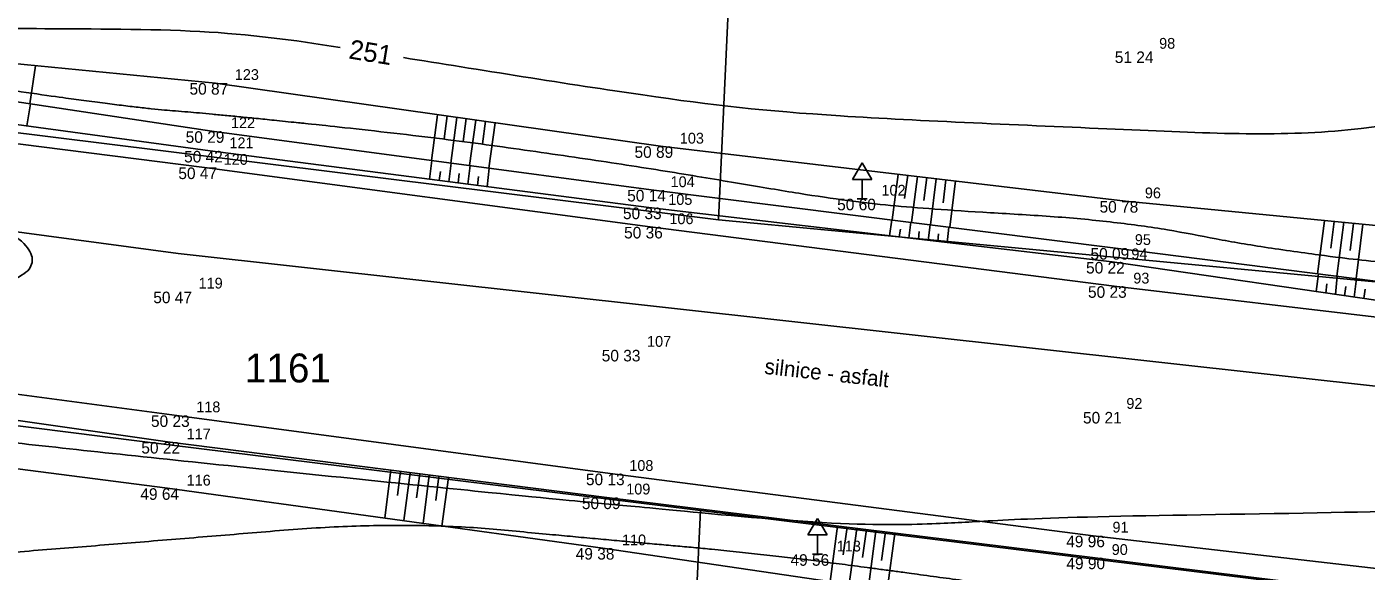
# Model space of a CAD drawing. Extents: x -704057 to -703795, y -1008732 to -1008584.
# Drawn here: x -703910.66 to -703875.92, y -1008669.28 to -1008655.16 of the extents above; entities that cross this region are included whole.
import ezdxf

# ---------------------------------------------------------------- set-up
doc = ezdxf.new("R2010")
doc.units = 0
for name, color, linetype in [('Z_body', 7, 'Continuous'), ('Z_body_cisla', 7, 'Continuous'), ('Z_body_vysky', 7, 'Continuous'), ('Z_dopravni_znaceni', 7, 'Continuous'), ('Z_katastr_cisla_pozemkove', 7, 'Continuous'), ('Z_katastr_hranice', 7, 'Continuous'), ('Z_katastr_hranice_KU', 7, 'Continuous'), ('Z_katastr_vnitrni_kresba', 7, 'Continuous'), ('Z_komunikace_zpevn_pl', 7, 'Continuous'), ('Z_popis', 7, 'Continuous'), ('Z_teren_hrany_paty', 7, 'Continuous'), ('Z_vrstevnice_popis', 7, 'Continuous'), ('Z_vrstevnice_vedlejsi', 7, 'Continuous')]:
    doc.layers.add(name, color=color, linetype=linetype)

# ---------------------------------------------------------------- blocks, each defined once
blk = doc.blocks.new('POINT_DISPLAY')
blk.add_line((0, 0), (0, 0))
blk = doc.blocks.new('Z527')
for p, q in [((0, 0.93), (-0.25, 0.5)), ((0.25, 0.5), (0, 0.93)), ((-0.25, 0.5), (0.25, 0.5)), ((0, 0), (0, 0.5)), ((-0.13, 0), (0.13, 0))]:
    blk.add_line(p, q)

msp = doc.modelspace()

# ---------------------------------------------------------------- linework, layer by layer
at = {"layer": 'Z_katastr_hranice'}
for p, q in [((-703892.72, -1008660.17), (-703891.93, -1008643.46)), ((-703913.69, -1008657.56), (-703892.72, -1008660.17)), ((-703892.72, -1008660.17), (-703821.1, -1008666.93)), ((-703947.65, -1008660.85), (-703907.73, -1008665.91)), ((-703907.73, -1008665.91), (-703871.83, -1008670.35))]:
    msp.add_line(p, q, dxfattribs=at)
at = {"layer": 'Z_katastr_hranice_KU'}
for p, q in [((-703947.15, -1008655.63), (-703906.73, -1008661.04)), ((-703906.73, -1008661.04), (-703853.02, -1008667))]:
    msp.add_line(p, q, dxfattribs=at)
at = {"layer": 'Z_katastr_vnitrni_kresba'}
msp.add_line((-703894.62, -1008696.05), (-703893.18, -1008667.71), dxfattribs=at)
at = {"layer": 'Z_komunikace_zpevn_pl'}
for p, q in [((-703906.05, -1008658.81), (-703916.99, -1008657.43)), ((-703894.49, -1008660.35), (-703906.05, -1008658.81)), ((-703882.46, -1008661.89), (-703894.49, -1008660.35)), ((-703870.13, -1008663.35), (-703882.46, -1008661.89)), ((-703917.71, -1008663.78), (-703906.76, -1008665.24)), ((-703906.76, -1008665.24), (-703895.53, -1008666.75)), ((-703895.53, -1008666.75), (-703883, -1008668.36)), ((-703883, -1008668.36), (-703870.95, -1008669.76))]:
    msp.add_line(p, q, dxfattribs=at)
at = {"layer": 'Z_teren_hrany_paty'}
for p, q in [((-703905.76, -1008656.62), (-703912.17, -1008656)), ((-703910.43, -1008656.17), (-703910.58, -1008657.16)), ((-703913.61, -1008656.7), (-703905.86, -1008657.87)), ((-703894.22, -1008658.26), (-703905.76, -1008656.62)), ((-703910.65, -1008657.73), (-703910.56, -1008657.16)), ((-703905.9, -1008658.38), (-703913.8, -1008657.3)), ((-703900, -1008657.44), (-703900.16, -1008658.63)), ((-703899.75, -1008657.47), (-703899.83, -1008658.07)), ((-703899.5, -1008657.51), (-703899.66, -1008658.7)), ((-703899.26, -1008657.54), (-703899.34, -1008658.14)), ((-703899.01, -1008657.58), (-703899.17, -1008658.76)), ((-703898.76, -1008657.61), (-703898.84, -1008658.2)), ((-703898.51, -1008657.65), (-703898.67, -1008658.83)), ((-703905.86, -1008657.87), (-703894.46, -1008659.39)), ((-703894.52, -1008659.85), (-703905.9, -1008658.38)), ((-703882.16, -1008659.68), (-703894.22, -1008658.26)), ((-703900.21, -1008659.11), (-703900.15, -1008658.63)), ((-703899.71, -1008659.18), (-703899.65, -1008658.7)), ((-703899.22, -1008659.24), (-703899.16, -1008658.76)), ((-703898.72, -1008659.31), (-703898.66, -1008658.83)), ((-703899.96, -1008659.15), (-703899.93, -1008658.91)), ((-703899.47, -1008659.21), (-703899.44, -1008658.97)), ((-703898.97, -1008659.28), (-703898.94, -1008659.04)), ((-703888.06, -1008658.99), (-703888.21, -1008660.17)), ((-703887.81, -1008659.01), (-703887.89, -1008659.61)), ((-703887.56, -1008659.04), (-703887.71, -1008660.24)), ((-703887.31, -1008659.07), (-703887.39, -1008659.67)), ((-703887.07, -1008659.1), (-703887.22, -1008660.3)), ((-703886.82, -1008659.13), (-703886.89, -1008659.73)), ((-703886.57, -1008659.16), (-703886.72, -1008660.36)), ((-703894.46, -1008659.39), (-703882.42, -1008660.9)), ((-703882.51, -1008661.26), (-703894.52, -1008659.85)), ((-703869.72, -1008660.9), (-703882.16, -1008659.68)), ((-703888.28, -1008660.58), (-703888.22, -1008660.17)), ((-703887.78, -1008660.64), (-703887.73, -1008660.23)), ((-703877, -1008660.19), (-703877.18, -1008661.57)), ((-703876.75, -1008660.21), (-703876.84, -1008660.9)), ((-703876.5, -1008660.23), (-703876.68, -1008661.63)), ((-703876.25, -1008660.26), (-703876.34, -1008660.96)), ((-703876.01, -1008660.28), (-703876.18, -1008661.69)), ((-703888.03, -1008660.61), (-703888, -1008660.41)), ((-703887.53, -1008660.67), (-703887.51, -1008660.47)), ((-703887.28, -1008660.7), (-703887.23, -1008660.3)), ((-703887.03, -1008660.73), (-703887.01, -1008660.53)), ((-703886.79, -1008660.76), (-703886.74, -1008660.36)), ((-703882.42, -1008660.9), (-703870.05, -1008662.47)), ((-703870.14, -1008663.06), (-703882.51, -1008661.26)), ((-703877.22, -1008662.03), (-703877.16, -1008661.57)), ((-703876.72, -1008662.1), (-703876.67, -1008661.63)), ((-703876.97, -1008662.07), (-703876.94, -1008661.83)), ((-703876.48, -1008662.14), (-703876.45, -1008661.9)), ((-703876.23, -1008662.17), (-703876.17, -1008661.69)), ((-703875.98, -1008662.21), (-703875.95, -1008661.97)), ((-703907.01, -1008665.93), (-703917.78, -1008664.39)), ((-703918.14, -1008665.69), (-703907.01, -1008667.13)), ((-703895.61, -1008667.37), (-703907.01, -1008665.93)), ((-703901.21, -1008666.66), (-703901.37, -1008667.9)), ((-703900.96, -1008666.69), (-703901.04, -1008667.32)), ((-703900.71, -1008666.73), (-703900.88, -1008667.97)), ((-703900.46, -1008666.76), (-703900.55, -1008667.38)), ((-703900.22, -1008666.79), (-703900.38, -1008668.04)), ((-703899.97, -1008666.82), (-703900.05, -1008667.45)), ((-703899.72, -1008666.85), (-703899.89, -1008668.11)), ((-703907.01, -1008667.13), (-703895.72, -1008668.68)), ((-703883.02, -1008668.93), (-703895.61, -1008667.37)), ((-703889.63, -1008668.11), (-703889.82, -1008669.55)), ((-703889.38, -1008668.14), (-703889.48, -1008668.86)), ((-703889.13, -1008668.17), (-703889.33, -1008669.62)), ((-703888.88, -1008668.2), (-703888.98, -1008668.93)), ((-703888.64, -1008668.23), (-703888.83, -1008669.69)), ((-703888.39, -1008668.26), (-703888.49, -1008669)), ((-703888.14, -1008668.3), (-703888.34, -1008669.77)), ((-703895.72, -1008668.68), (-703883.41, -1008670.49)), ((-703871.14, -1008670.4), (-703883.02, -1008668.93))]:
    msp.add_line(p, q, dxfattribs=at)
at = {"layer": 'Z_vrstevnice_popis'}
for points in [[(-703958.782, -1008656.452), (-703958.711, -1008656.345), (-703958.126, -1008655.591), (-703956.246, -1008655.482), (-703959.788, -1008654.246), (-703961.93, -1008651.293), (-703961.78, -1008651.126), (-703959.248, -1008651.187), (-703958.2, -1008651.305), (-703958.136, -1008651.315), (-703958.106, -1008651.318), (-703958.062, -1008651.325), (-703957.976, -1008651.334), (-703949.197, -1008652.35), (-703949.055, -1008652.366), (-703948.978, -1008652.372), (-703948.89, -1008652.368), (-703940.582, -1008653.06), (-703940.108, -1008653.095), (-703933.647, -1008653.758), (-703931.403, -1008653.997), (-703930.745, -1008653.985), (-703930.26, -1008654), (-703929.245, -1008652.825), (-703928.701, -1008652.453), (-703928.643, -1008652.6), (-703928.429, -1008652.279), (-703926.218, -1008652.574), (-703924.884, -1008652.504), (-703924.716, -1008652.484), (-703922.063, -1008653.995), (-703921.911, -1008654.006), (-703921.781, -1008654.024), (-703921.558, -1008654.048), (-703920.173, -1008654.162), (-703919.91, -1008654.188), (-703916.508, -1008654.023), (-703914.694, -1008654.331), (-703914.465, -1008654.432), (-703913.706, -1008654.968), (-703913.145, -1008655.151), (-703910.497, -1008655.228), (-703905.972, -1008655.203), (-703903.752, -1008655.504), (-703902.532, -1008655.695)], [(-703900.886, -1008655.959), (-703899.024, -1008656.26), (-703894.071, -1008657.056), (-703890.313, -1008657.487), (-703881.983, -1008657.824), (-703876.324, -1008658.109), (-703871.084, -1008656.76), (-703869.237, -1008656.583), (-703868.601, -1008656.623), (-703856.36, -1008656.952), (-703852.392, -1008657.193), (-703842.819, -1008657.404), (-703836.655, -1008657.542), (-703831.19, -1008657.812), (-703826.999, -1008658.179), (-703824.254, -1008658.442), (-703823.966, -1008658.47)], [(-703935.451, -1008665.426), (-703935.149, -1008665.04), (-703935.119, -1008664.898), (-703935.079, -1008664.688), (-703934.778, -1008664.597), (-703933.704, -1008664.644), (-703930.729, -1008663.86), (-703930.56, -1008663.863), (-703922.686, -1008664.709), (-703917.99, -1008665.148), (-703912.22, -1008665.818), (-703907.01, -1008666.385), (-703897.89, -1008667.322), (-703895.624, -1008667.536), (-703894.683, -1008667.62), (-703889.646, -1008668.109), (-703886.88, -1008668.055), (-703885.948, -1008667.981), (-703882.942, -1008667.846), (-703876.005, -1008667.766), (-703871.926, -1008667.612), (-703869.247, -1008667.54), (-703868.688, -1008667.52)]]:
    msp.add_open_spline(points, degree=3, dxfattribs=at)
at = {"layer": 'Z_vrstevnice_vedlejsi'}
for points in [[(-703944.218, -1008669.537), (-703942.215, -1008669.847), (-703941.835, -1008669.79), (-703940.983, -1008669.911), (-703940.538, -1008669.059), (-703940.441, -1008669.011), (-703939.659, -1008668.87), (-703938.392, -1008666.573), (-703937.218, -1008665.198), (-703936.994, -1008664.158), (-703936.811, -1008663.182), (-703935.504, -1008662.788), (-703930.851, -1008662.989), (-703930.683, -1008662.945), (-703930.514, -1008662.948), (-703928.53, -1008663.14), (-703926.451, -1008662.869), (-703924.285, -1008662.962), (-703918.453, -1008660.188), (-703917.529, -1008662.583), (-703908.804, -1008661.73), (-703914.417, -1008658.58), (-703914.255, -1008657.775), (-703916.458, -1008657.408), (-703916.075, -1008656.975), (-703916.505, -1008656.883), (-703916.435, -1008655.703), (-703915.746, -1008656.007), (-703915.438, -1008656.225), (-703913.541, -1008656.36), (-703913.202, -1008656.502), (-703907.93, -1008657.256), (-703905.824, -1008657.417), (-703900.033, -1008658.024), (-703894.345, -1008658.848), (-703890.179, -1008659.57), (-703887.702, -1008659.871), (-703882.266, -1008660.175), (-703878.347, -1008660.959), (-703873.149, -1008661.531), (-703869.803, -1008661.293), (-703867.148, -1008661.514), (-703856.66, -1008662.48), (-703848.555, -1008661.935), (-703843.582, -1008661.747), (-703840.018, -1008661.713), (-703835.656, -1008661.182), (-703832.168, -1008661.259), (-703831.497, -1008661.293), (-703819.488, -1008662.346), (-703817.521, -1008662.543), (-703807.841, -1008663.114), (-703805.78, -1008663.132)], [(-703806.645, -1008669.413), (-703810.064, -1008669.091), (-703818.896, -1008668.231), (-703821.949, -1008667.886), (-703832.348, -1008666.911), (-703832.429, -1008666.905), (-703837.82, -1008666.255), (-703832.713, -1008666.908), (-703832.355, -1008666.952), (-703825.705, -1008667.99), (-703819.056, -1008669.026), (-703815.993, -1008669.415), (-703810.462, -1008670.24), (-703806.87, -1008671.09), (-703808.766, -1008673.591), (-703809.75, -1008673.886), (-703817.454, -1008673.52), (-703819.628, -1008673.248), (-703826.836, -1008673.24), (-703833.27, -1008673.353), (-703835.286, -1008673.278), (-703844.44, -1008672.81), (-703850.152, -1008672.821), (-703855.806, -1008672.275), (-703857.13, -1008672.165), (-703860.162, -1008671.947), (-703871.237, -1008671.005), (-703876.973, -1008670.473), (-703883.276, -1008669.953), (-703888.652, -1008669.207), (-703892.007, -1008668.787), (-703895.701, -1008668.459), (-703900.931, -1008667.965), (-703907.22, -1008668.487), (-703913.351, -1008668.979), (-703918.495, -1008669.549), (-703927.701, -1008668.863), (-703930.6, -1008669.724), (-703932.124, -1008670.909), (-703936.972, -1008673.376)]]:
    msp.add_open_spline(points, degree=2, dxfattribs=at)

# ---------------------------------------------------------------- block references
at = {"layer": 'Z_body'}
for p in [(-703881.79, -1008655.8), (-703905.76, -1008656.62), (-703905.86, -1008657.87), (-703905.9, -1008658.38), (-703894.22, -1008658.26), (-703906.05, -1008658.81), (-703894.46, -1008659.39), (-703894.52, -1008659.85), (-703888.99, -1008659.62), (-703882.16, -1008659.68), (-703894.49, -1008660.35), (-703882.42, -1008660.9), (-703882.51, -1008661.26), (-703882.46, -1008661.89), (-703906.7, -1008662.03), (-703895.07, -1008663.54), (-703906.76, -1008665.24), (-703882.64, -1008665.15), (-703907.01, -1008665.93), (-703895.53, -1008666.75), (-703907.01, -1008667.13), (-703895.61, -1008667.37), (-703883, -1008668.36), (-703895.72, -1008668.68), (-703890.15, -1008668.84), (-703883.02, -1008668.93)]:
    msp.add_blockref('POINT_DISPLAY', p, dxfattribs=at)
at = {"layer": 'Z_dopravni_znaceni'}
for p in [(-703888.99, -1008659.62), (-703890.15, -1008668.84)]:
    msp.add_blockref('Z527', p, dxfattribs=at)

# ---------------------------------------------------------------- texts
at = {"layer": 'Z_body_cisla'}
for s, p in [('98', (-703881.29, -1008655.73)), ('123', (-703905.26, -1008656.54)), ('122', (-703905.36, -1008657.79)), ('121', (-703905.4, -1008658.31)), ('103', (-703893.72, -1008658.19)), ('120', (-703905.55, -1008658.74)), ('104', (-703893.96, -1008659.32)), ('105', (-703894.02, -1008659.78)), ('102', (-703888.49, -1008659.54)), ('96', (-703881.66, -1008659.61)), ('106', (-703893.99, -1008660.28)), ('95', (-703881.92, -1008660.82)), ('94', (-703882.01, -1008661.19)), ('119', (-703906.2, -1008661.95)), ('93', (-703881.96, -1008661.82)), ('107', (-703894.57, -1008663.46)), ('92', (-703882.14, -1008665.07)), ('118', (-703906.26, -1008665.16)), ('117', (-703906.51, -1008665.86)), ('108', (-703895.03, -1008666.68)), ('116', (-703906.51, -1008667.06)), ('109', (-703895.11, -1008667.29)), ('91', (-703882.5, -1008668.28)), ('110', (-703895.22, -1008668.61)), ('113', (-703889.65, -1008668.77)), ('90', (-703882.52, -1008668.86))]:
    msp.add_text(s, height=0.28, dxfattribs=at).set_placement(p)
at = {"layer": 'Z_body_vysky'}
for s, p in [('51 24', (-703882.44, -1008656.1)), ('50 87', (-703906.435, -1008656.92)), ('50 29', (-703906.535, -1008658.17)), ('50 42', (-703906.575, -1008658.68)), ('50 89', (-703894.895, -1008658.56)), ('50 47', (-703906.725, -1008659.11)), ('50 14', (-703895.085, -1008659.69)), ('50 33', (-703895.195, -1008660.15)), ('50 60', (-703889.64, -1008659.92)), ('50 78', (-703882.835, -1008659.98)), ('50 36', (-703895.165, -1008660.65)), ('50 09', (-703883.07, -1008661.2)), ('50 22', (-703883.185, -1008661.56)), ('50 23', (-703883.135, -1008662.19)), ('50 47', (-703907.375, -1008662.33)), ('50 33', (-703895.745, -1008663.84)), ('50 21', (-703883.265, -1008665.45)), ('50 23', (-703907.435, -1008665.54)), ('50 22', (-703907.685, -1008666.23)), ('50 13', (-703896.155, -1008667.05)), ('49 64', (-703907.71, -1008667.43)), ('50 09', (-703896.26, -1008667.67)), ('49 96', (-703883.7, -1008668.66)), ('49 38', (-703896.42, -1008668.98)), ('49 56', (-703890.85, -1008669.14)), ('49 90', (-703883.695, -1008669.23))]:
    msp.add_text(s, height=0.3, dxfattribs=at).set_placement(p)
at = {"layer": 'Z_katastr_cisla_pozemkove'}
msp.add_text('1161', height=0.75, dxfattribs=at).set_placement((-703905, -1008664.385))
at = {"layer": 'Z_popis'}
msp.add_text('silnice - asfalt', height=0.4, rotation=353.7, dxfattribs=at).set_placement((-703891.54, -1008664.16))
at = {"layer": 'Z_vrstevnice_popis'}
msp.add_text('251', height=0.5, rotation=350.8451, dxfattribs=at).set_placement((-703902.325, -1008655.98))

doc.saveas('drawing.dxf')
